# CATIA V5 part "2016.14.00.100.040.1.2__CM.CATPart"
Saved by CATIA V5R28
Part number: 2016.14.00.100.040.1.2__CM
Property "id_number": "2016.14.00.100.040.1.2"
Publications: "Absolute Axis System", "driver", "slider", "base", "cam diagram"
Bounding box of the stored display mesh (mm): x -40 to 190, y -87.5 to 87.5, z -5 to 235
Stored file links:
  N:\B2\Normteile\K\2016\11-14\010\cm\2016.14.00.100.040.1.2__CM.CATPart
  H:\CAD_Startmodelle\Tests\fill-in_PRT-SL_TEMPLATE.xlsx
  H:\CAD_Startmodelle\V5-R24\R24_TEMPLATE_PRT_FIBRO_CAM_TECNOLOGIES_INDEX.xlsx
  H:\z_Einordnen\170511__Anfrage_TK_HN\170511__CC01_TKHN.CATPart
  N:\B2\Normteile\K\2016\9xxx\2016.9024.1705.001\Entwurf_\170511__CC01_TKHN.CATPart
  N:\B2\Normteile\K\2016\9xxx\2016.9024.1707.006\Konstruktion\2016.9024.1707.006__HP__CUSTOMIZED_CAM_CM.CATPart
  N:\B2\Normteile\K\2016\9xxx\2016.9024.1707.005\Konstruktion\2016.9024.1707.005__HP__CUSTOMIZED_CAM_CM.CATPart
  N:\B2\Normteile\K\2016\9xxx\2016.9024.1707.008\Konstruktion\2016.9024.1707.008__HP__CUSTOMIZED_CAM_CM.CATPart
  N:\B2\Normteile\K\2016\9xxx\2016.9024.1707.009\Konstruktion\2016.9024.1707.009__HP__CUSTOMIZED_CAM_CM.CATPart
  N:\B2\Normteile\K\2016\9xxx\2016.9024.1707.010\Konstruktion\2016.9024.1707.010__HP__CUSTOMIZED_CAM_CM.CATPart
  N:\B2\Normteile\K\2016\9xxx\2016.9024.1708.002\Konstruktion\2016.9024.1708.002__HP__CUSTOMIZED_CAM_CM.CATPart
  N:\B2\Normteile\K\2016\9xxx\2016.9024.1802.001\Konstruktion\2016.9024.1802.001__HP__CUSTOMIZED_CAM_CM.CATPart
  N:\B2\Normteile\K\2016\9xxx\2016.9024.1802.002\Konstruktion\2016.9024.1802.002__HP__CUSTOMIZED_CAM_CM.CATPart
  N:\B2\Normteile\K\2016\9xxx\2016.9024.1811.003\Konstruktion\2016.9024.1811.003__HP__CUSTOMIZED_CAM_CM.CATPart
  N:\B2\Normteile\K\2016\9xxx\2016.9015.1811.001\Konstruktion\am\2016.9015.1811.001__AM__FCC_HV_DMC_0125-00.CATPart
  N:\B2\Normteile\K\2016\9xxx\2016.9024.1811.009\Konstruktion\2016.9024.1811.009__HP__CUSTOMIZED_CAM_CM.CATPart
  N:\B2\Normteile\K\2016\9xxx\2016.9024.1911.002\Konstruktion\am\2016.9024.1911.002__AM__CUSTOMIZED_CAM_CM.CATPart
  N:\B2\Normteile\K\2016\9xxx\2016.9024.2002.006\Konstruktion\2016.9024.2002.006__AM.CATPart
  N:\B2\Normteile\K\2016\9xxx\2016.9024.2004.001\Konstruktion\2016.9024.2004.001__AM__FCC_HV_CAEC_0260-45.CATPart
  N:\B2\Normteile\K\2016\9xxx\2016.9024.2006.002\Konstruktion\2016.9024.2006.002__AM__FCC_HV_CAEC_0260-40.CATPart
  N:\B2\Normteile\K\2016\9xxx\2016.9024.2006.005\Konstruktion\am\2016.9024.2006.005__AM__CFCC_HV_AEPC_0080-65.CATPart
  N:\B2\Normteile\K\2016\9xxx\2016.9024.2006.004\Konstruktion\am\2016.9024.2006.004__AM__CFCC_HV_AEC_0210-35.CATPart
  N:\B2\Normteile\K\2016\9xxx\2016.9026.2006.001\Konstruktion\am\2016.9026.2006.001__AM__FCC_LV_CAEC_0180-40.CATPart
  N:\B2\Normteile\K\2016\9xxx\2016.9015.2007.001\Konstruktion\am\2016.9015.2007.001__AM__FCC_HV_CDMPC_0090-00.CATPart
  N:\B2\Normteile\K\2016\9xxx\2016.9024.2005.001\Konstruktion\am\2016.9024.2005.001__AM__CFCC_HV_AEPC_1400-70.CATPart
  N:\B2\Normteile\K\2016\9xxx\2016.9024.2007.004\Konstruktion\am\2016.9024.2007.004__AM__CFCC_HV_AEC_1250-80.CATPart
  N:\B2\Normteile\K\2016\11-14\005\2016.11.00.052.040.1.02__AS__DIE_MOUNT_CAM__W52_A0_S40.CATProduct
  N:\B2\Normteile\K\2016\11-14\cm\005\catia\2016.11.00.052.025.1.2__CM.CATPart
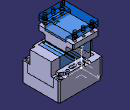
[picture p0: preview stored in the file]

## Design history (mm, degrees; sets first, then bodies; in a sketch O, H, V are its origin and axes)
Parameters
  group "process_parameters"
    modeltype = ""
    stocklist = ""
    id_number = "2016.14.00.100.040.1.2"
    id_number_rough_part = ""
    revision_index = ""
    revision_date = ""
    revision_description = ""
    category = ""
    material = ""
    manufacturing_information = ""
    standard = ""
  group "release_parameters_startmodel"
    sm_revision_index = "2016_00" {design table}
    sm_revision_date = "20.08.2016" {design table}
    sm_revision_name = "Meyer" {design table}
    sm_revision_description = "new part template FIBRO cam tecnologies" {design table}
AxisSystem1: origin (0, 0, 0), X (1, 0, 0), Y (0, 1, 0), Z (0, 0, 1)
Set1 "reference elements"
  Sketch1 "cam diagram" on ZX plane of AxisSystem1, origin (0, 0, 0), H (-1, 0, 0), V (0, 0, 1)
    line L1 (0, 0) -> (40, 0)
    line L2 (40, 0) -> (0, 40)
    point P2 (0, 40)
    line L3 (0, 40) -> (0, 0)
    length L1 = 40
    angle H L2 = 45
    horizontal: L1 H
    coincidence: P2 V
    vertical: L3 V
Body1 "finished_part" (main body)
  Body2 "rough_part"
  Add1 "rough_part": tool Body2
  Body3 "milling operations"
  Remove1 "milling operations": tool Body3
  Body4 "drilling operations"
  Remove2 "drilling operations": tool Body4
Body5 "driver"
  Solid1: solid without history
Body6 "slider"
  Solid2: solid without history
Body7 "base"
  Solid3: solid without history
Body8 "opened position"
  Body9 "slider"
    Body10 "slider"
      Solid4: linked copy from another document
    Assemble1: tool Body10
    Translate1: FirstPoint vertex [element of Sketch1 | element of Sketch1], SecondPoint vertex [element of Sketch1 | element of Sketch1], ToTransfor Assemble1
  Assemble2: tool Body9
  Body11 "driver"
    Body12 "driver"
      Solid5: linked copy from another document
    Assemble3: tool Body12
    Translate2: FirstPoint vertex [element of Sketch1 | element of Sketch1], SecondPoint vertex [element of Sketch1 | element of Sketch1], ToTransfor Assemble3
  Assemble4: tool Body11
